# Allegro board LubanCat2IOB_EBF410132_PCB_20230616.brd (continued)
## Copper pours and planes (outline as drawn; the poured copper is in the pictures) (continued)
N17409816 on BOTTOM: 130.94,57.27 129.92,57.27 129.77,57.43 129.77,58.44 130.38,59.05 130.38,61.54 128.14,61.54 128.14,60.19 128.8,60.19 128.98,60.02 128.98,56.87 129.24,56.61 130.94,56.61
N17410026 on BOTTOM: 128.57,59.41 127.36,59.41 127.23,59.28 127.23,57.68 127.36,57.55 128.52,57.55 128.57,57.6
N17468430 on BOTTOM: 18.8,86.08 21.23,86.08 21.23,85.39 21.44,85.19 21.92,85.19 21.92,83.92 21.01,83.92 20.75,84.17 20.75,84.91 20.47,85.19 17.6,85.19 17.6,86.66 18.21,86.66
N17485853 on TOP: 137.92,61.67 138,61.49 138.18,61.41 138.79,61.41 138.97,61.49 139.04,61.67 139.04,63.27 138.97,63.45 138.79,63.52 138.18,63.52 138,63.45 137.92,63.27
N17485857 on TOP: 135.64,61.24 136.63,61.24 136.78,61.39 136.78,63.98 136.55,64.21 136.02,64.21 136.02,65.63 138.3,65.63 138.3,64.23 137.97,64.23 137.72,63.98 137.72,60.75 137.52,60.55 135.64,60.55
N17577092 on TOP: 118.08,22.81 118.08,21.89 119.96,21.89 120.07,21.99 120.07,22.7 119.96,22.81
N17577104 on TOP: 117.12,25.19 117.12,23.34 117.35,23.11 120.55,23.11 120.7,22.96 120.7,22.4 122.07,22.4 122.07,24.68 120.68,24.68 120.68,24.18 120.55,24.05 117.98,24.05 117.83,24.2 117.83,25.19
N17590789 on BOTTOM (solid shape): 34.62,92.35 34.71,92.39 34.8,92.35 35.51,91.64 34.71,90.55 33.91,91.64
N17590789 on BOTTOM (solid shape): 35.46,89.7 35.5,89.79 35.59,89.83 36.86,89.78 36.73,88.66 35.46,88.68
N17590789 on BOTTOM (solid shape): 35.95,90.58 35.95,89.47 35.91,89.37 35.81,89.34 34.54,89.49 34.68,90.61
N17590802 on BOTTOM (solid shape): 36.84,93.35 35.67,93.09 35.56,93.12 35.51,93.22 35.51,94.25 36.73,94.31
N17590849 on BOTTOM (solid shape): 36.27,85.12 36.32,84.98 36.27,84.85 35.63,84.21 34.66,84.98 35.63,85.76
N17804594 on TOP: 4.55,76.27 7.04,76.27 7.14,76.17 7.14,75.46 7.04,75.36 4.55,75.36
N17804606 on TOP: 3.61,78.66 3.61,76.68 3.76,76.53 8.26,76.53 8.41,76.37 8.41,75.87 9.8,75.87 9.8,78.15 5.69,78.15 5.54,78 5.54,77.67 5.44,77.57 4.39,77.57 4.29,77.67 4.29,78.66

Small or netless copper shapes (teardrops, artwork), in the pictures only: 60 on TOP, 31 on BOTTOM, 1 on ART03

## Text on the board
Ref Des/Silkscreen Bottom: T1IN | R1OUT | T7_TX | T7_RX | U7_TX | U7_RX | T2IN | R2OUT | T9TX | T9RX | U9TX | U9RX | 5V | GND | 12V | SIM Card | SD Card | CAM0 | CAM1 | RX | TX | NC | VIN7 | SDA_M0 | VIN6 | SCL_M0 | RESET | VIN5 | VIN4 | TP_INT | 3V3 | VIN1 | 20230616 | EBF410132
User.Comments: CR_1_2 | CR_UNNAMED_13 | CR_UNNAMED_5 | CR_UNNAMED_9
Ref Des/Silkscreen Top: DEBUG | RESET | GND | 3V3 | POWER OUT | ON/OFF | 5V | RTC | RECOVERY | 12V | USB_OTG | FAN | 2_L | 2_H | CAN | 1_L | EAR | SPK | 1_H | 2_A | MIC | 2_B | RS485 | 1_A | 1_B | HDMI | T1OUT | R1IN | RS232 | T2OUT | ETH0 | R2IN | ETH1 | UART9 | UART7 | SARADC | EDP_TP | MINI PCIE | USB2.0 HOST | USB3.0/USB2.0 HOST | SATA_POWER | EBF410132 | 20230616 | PWR | B | A | USR | M.2 PCIE3.0 | IR | TX | RX | DC_12V | SATA | 30 | MIPI DSI TX0 | MIPI DSI TX1 | EDP
DEVICE_TYPE_BOTTOM: R18 | R13 | R31 | C96 | R30 | C161 | C160 | C156 | C159 | C155 | C158 | C157 | C154 | R40 | R48 | R47 | R46 | R45 | R44 | R43 | U3 | R52 | R56 | R58 | R57 | C180 | C48 | SS3 | SS4 | C41 | Y1 | C42 | L23 | U6 | L5 | U2 | L9 | L4 | L2 | C62 | C57 | C2 | C166 | U5 | C5 | C106 | C103 | L1 | L3 | C74 | R60 | C10 | R61 | R62 | R63 | R64 | R65 | R67 | R66 | R42 | C128 | R59 | R51 | C138 | C242 | R50 | C175 | SS2 | SS1 | Y2 | C95 | C97 | R32 | R38 | R39 | L8 | L7 | C43 | C39 | C47 | R10 | C244 | C235 | C34 | C29 | C30 | R6 | R7 | R2 | C13 | C12 | C14 | C84 | U1 | C28 | C83 | R76 | C17 | C26 | C234 | C8 | R73 | J5 | C179 | U4 | C50 | MASKROM | 45 | 62
DEVICE_TYPE_TOP: C55 | D4 | D3 | C58 | C238 | R72 | R81 | C35 | C15 | C40 | L6 | C46 | C44 | C49 | C38 | C52 | C36 | R24 | C61 | C56 | R22 | R25 | C225 | C230 | C67 | C60 | C109 | C6 | C99 | C23 | C22 | C21 | C3 | C51 | R19 | R21 | R77 | C227 | C231 | C232 | C9 | R1 | R3 | R4 | C25 | R5 | C24 | C27 | C80 | J3 | J1 | J4 | J2 | C176 | C193 | C182 | C202 | C200 | C196 | C212 | C183 | C184 | C177 | C239 | C204 | C209 | C189 | C224 | L22 | C240 | C241 | L11 | L13 | C102 | L14 | C100 | C119 | R68 | C108 | C146 | C123 | R41 | C170 | C169 | C163 | C111 | C71 | C81 | C136 | C135 | C69 | C75 | C78 | C66 | C72 | C130 | C134 | R36 | C131 | C144 | C73 | R33 | C116 | R55 | C107 | L10 | C90 | R54 | L15 | C91 | R53 | C85 | C86 | L12 | C214 | C205 | C191 | C195 | C217 | C198 | C207 | C181 | C188 | C206 | C192 | C190 | C218 | C53 | C243 | C237 | C54 | D1 | C236 | R20 | R8 | R26 | R27 | R9 | R80 | C229 | C37 | C18 | R23 | C33 | R79 | C228 | C63 | C16 | C31 | C7 | C59 | C32 | R16 | C68 | C19 | C45 | R11 | C1 | C4 | C11 | R74 | R15 | R75 | R12 | C233 | D2 | C20 | C226 | C79 | Q1 | R17 | R14 | C133 | C132 | C216 | C213 | C211 | C220 | C223 | R70 | C187 | R69 | C219 | C174 | C186 | U7 | C203 | C208 | C201 | C221 | R37 | R49 | C178 | C197 | R71 | C101 | R78 | R34 | L20 | R35 | L18 | C148 | L21 | C165 | C149 | L19 | C152 | L17 | C162 | C115 | C153 | C122 | L16 | C114 | C98 | C142 | C105 | C126 | C113 | C120 | C143 | C167 | C125 | C168 | C150 | C104 | C112 | C124 | C147 | C140 | C151 | C70 | C82 | C141 | C164 | C76 | C139 | C77 | C171 | C65 | C172 | C137 | C129 | C127 | C145 | C110 | C173 | C121 | C118 | C64 | C89 | C92 | C117 | C93 | C94 | C88 | C87 | R28 | R29 | C185 | C222 | C215 | C194 | C210 | C199 | 2 | 80 | 79 | EBF410131 | 20230329
User.8: FIGURE | SIZE | 12.0 | 19.685 | 21.654 | 25.591 | 27.559 | 29.528 | 31.496 | 33.465 | 35.43 | 39.37 | 47.244 | 59.055 | 62.0 | 72.047 | 78.74 | 94.488 | 125.98 | 166.142 | 23.622 | 25.59 | 35.433 | 40.0 | 43.307 | 62.992 | 74.803 | 125.984 | 127.953 | 47.24x23.62 | 66.93x23.62 | 86.61x39.37 | 106.299x35.429 | DRILL CHART: TOP to BOTTOM | ALL UNITS ARE IN MILS | PLATED | NON-PLATED | QTY | 1890 | 2 | 19 | 18 | 30 | 7 | 9 | 4 | 15 | 8 | 20 | 22 | 10 | 5 | 1
